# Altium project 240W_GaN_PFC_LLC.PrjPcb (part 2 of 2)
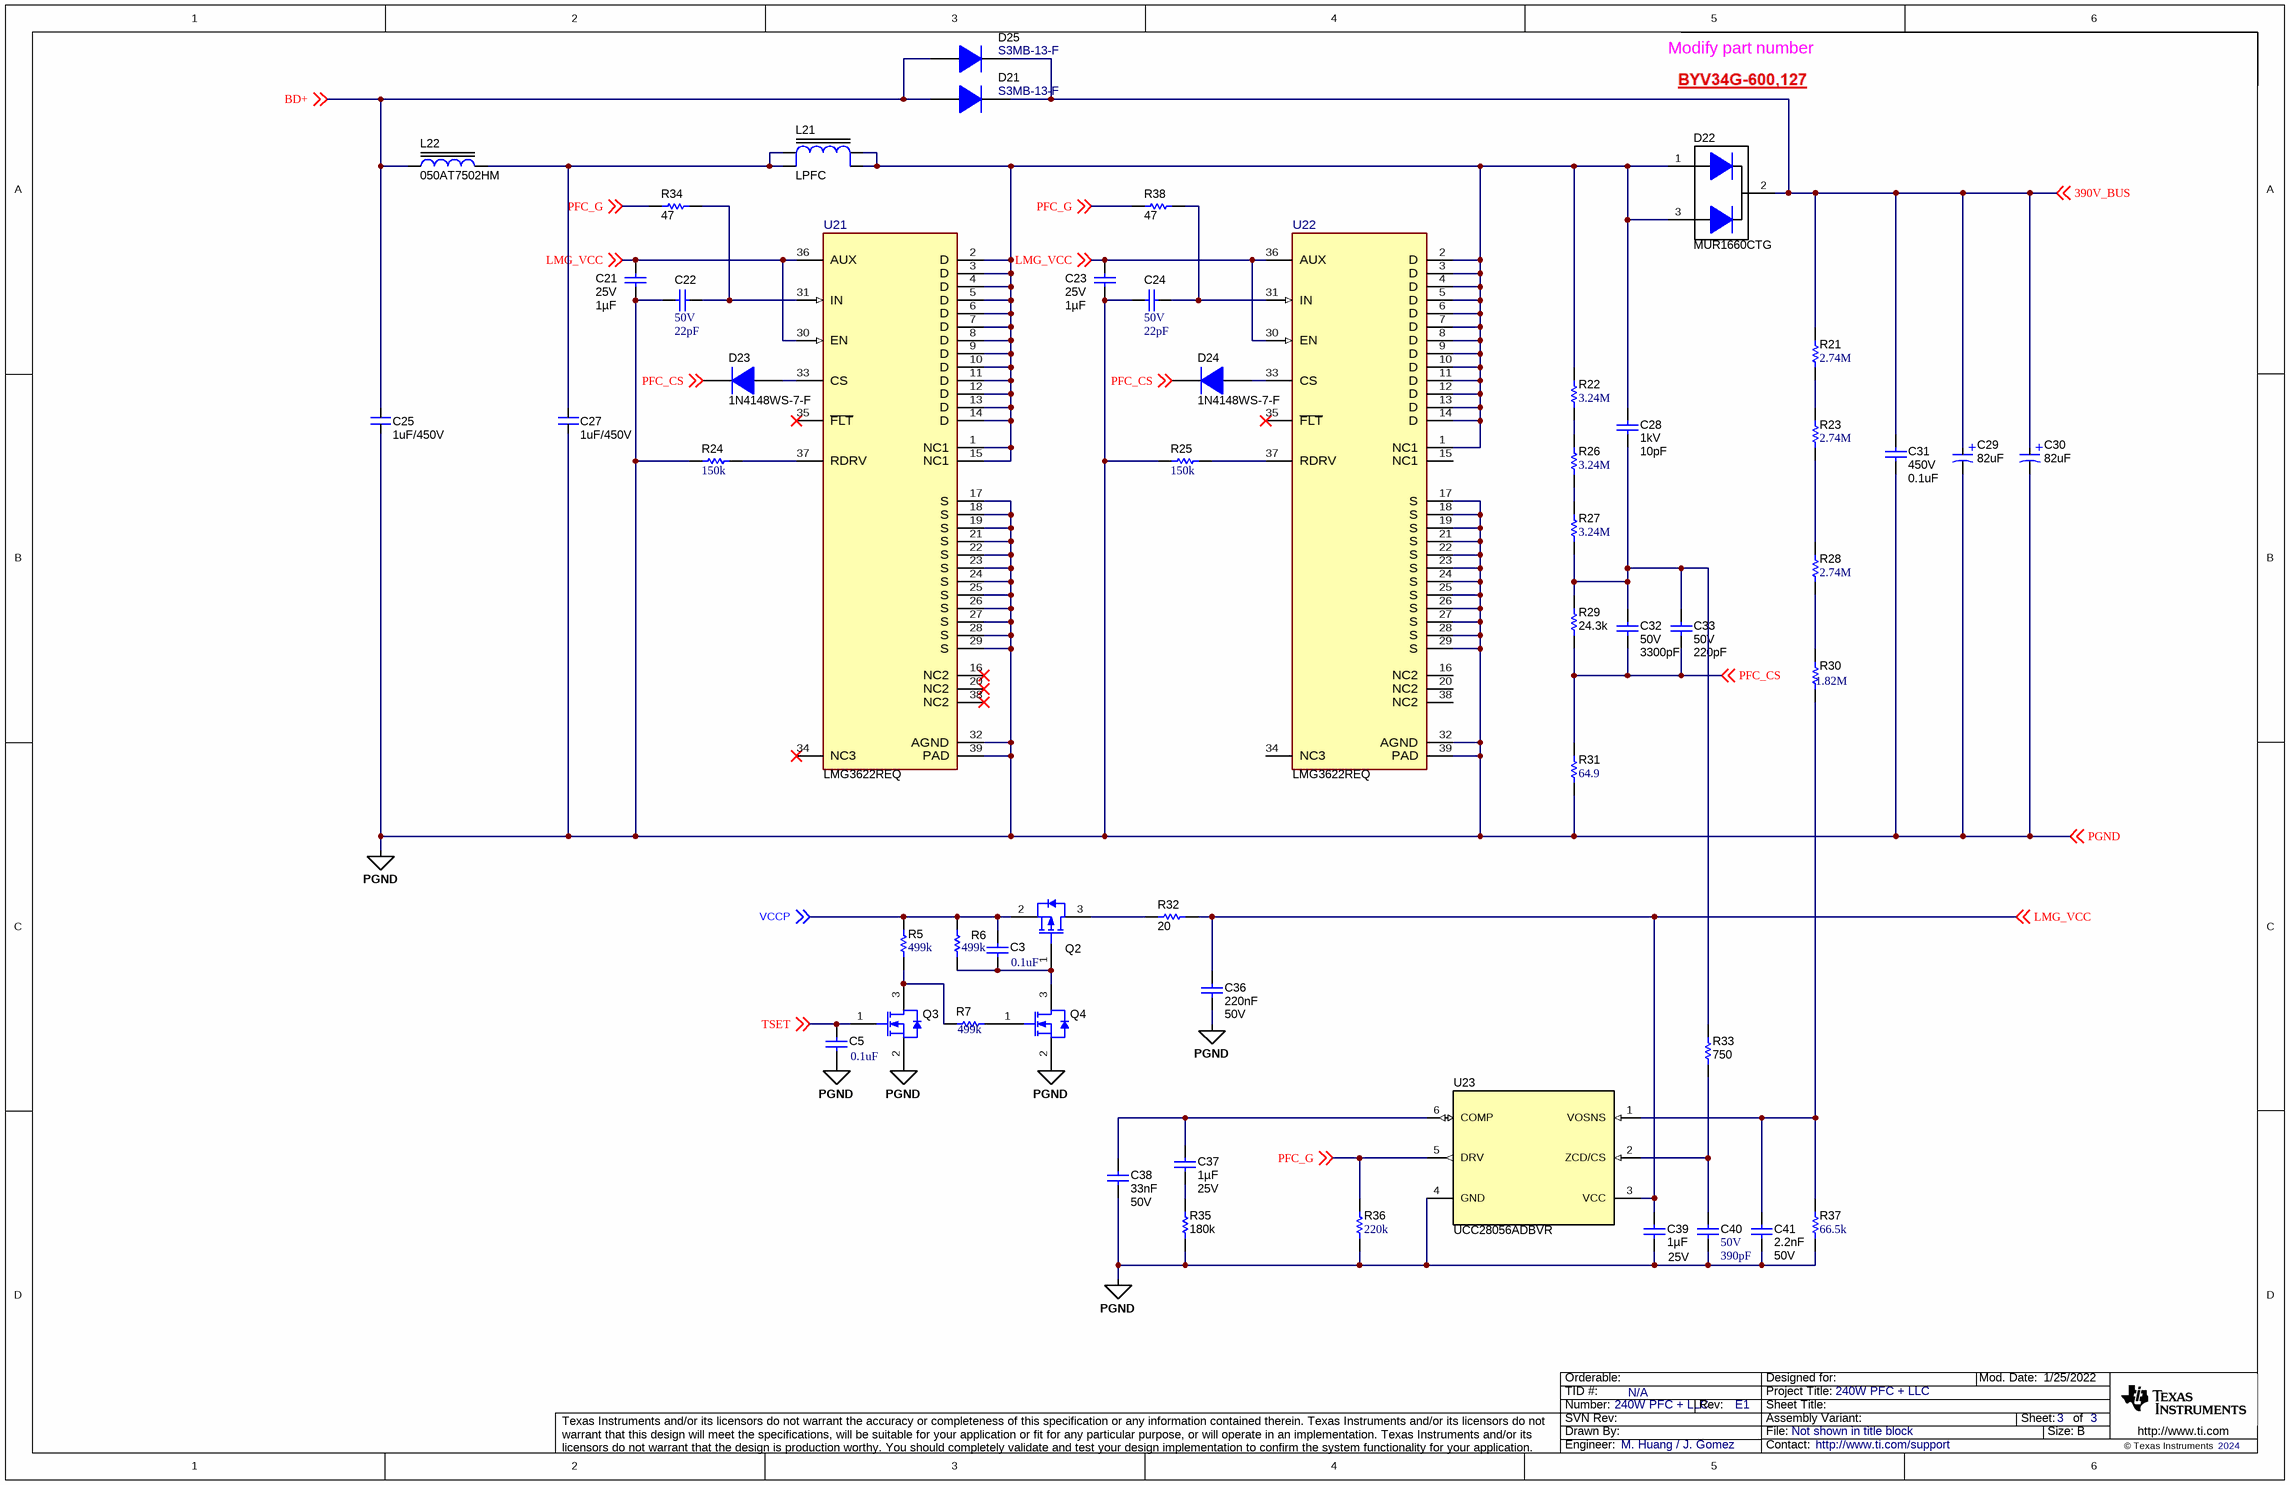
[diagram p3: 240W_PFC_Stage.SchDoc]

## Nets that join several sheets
PGND: 240W_GaN_PFC_LLC_AC_EMI (BD1.4 BD2.4), 240W_LLC_Stage (40 pins), 240W_PFC_Stage (52 pins)
RTN: 240W_GaN_PFC_LLC_AC_EMI (CY1.2 CY2.2), 240W_LLC_Stage (24 pins)
390V_BUS: 240W_LLC_Stage (17 pins), 240W_PFC_Stage (7 pins)
BD+: 240W_GaN_PFC_LLC_AC_EMI (BD1.1 BD2.1), 240W_PFC_Stage (C25.1 D21.2 D25.2 L22.1)
HV: 240W_GaN_PFC_LLC_AC_EMI (R2.1), 240W_LLC_Stage (U102.1)
TSET: 240W_LLC_Stage (R119.1 R121.2 U102.7), 240W_PFC_Stage (C5.1 Q3.1)
VCCP: 240W_LLC_Stage (9 pins), 240W_PFC_Stage (C3.1 Q2.2 R5.2 R6.2)

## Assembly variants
001: not fitted R116 R126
